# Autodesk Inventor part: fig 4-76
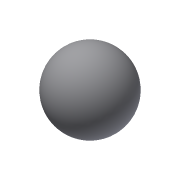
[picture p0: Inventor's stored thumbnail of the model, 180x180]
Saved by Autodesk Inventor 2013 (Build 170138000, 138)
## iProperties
Created: 2012-07
Part Number: fig 4-76
Material: Generic
Document SubType Name: Modeling
Designer: CADCIM
Density: 1 g/cm^3
Author: CADCIM
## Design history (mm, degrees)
sketch "Sketch1"
  geometry: L1 (7.807, -5.174)-(-7.807, 5.174); A1 r 9.366 centre (0, 0) between (7.807, -5.174) and (-7.807, 5.174)
  constraints: 2 end point, 2 point on circle, 1 centre point, 1 midpoint
  dimensions: "d0" = 90 deg dimension on A1.centre A1 L1.start L1.end L1
revolve "Revolution1" sketch "Sketch1" stored, may be unused: angle "d0" = 90 deg
body "Solid1"
